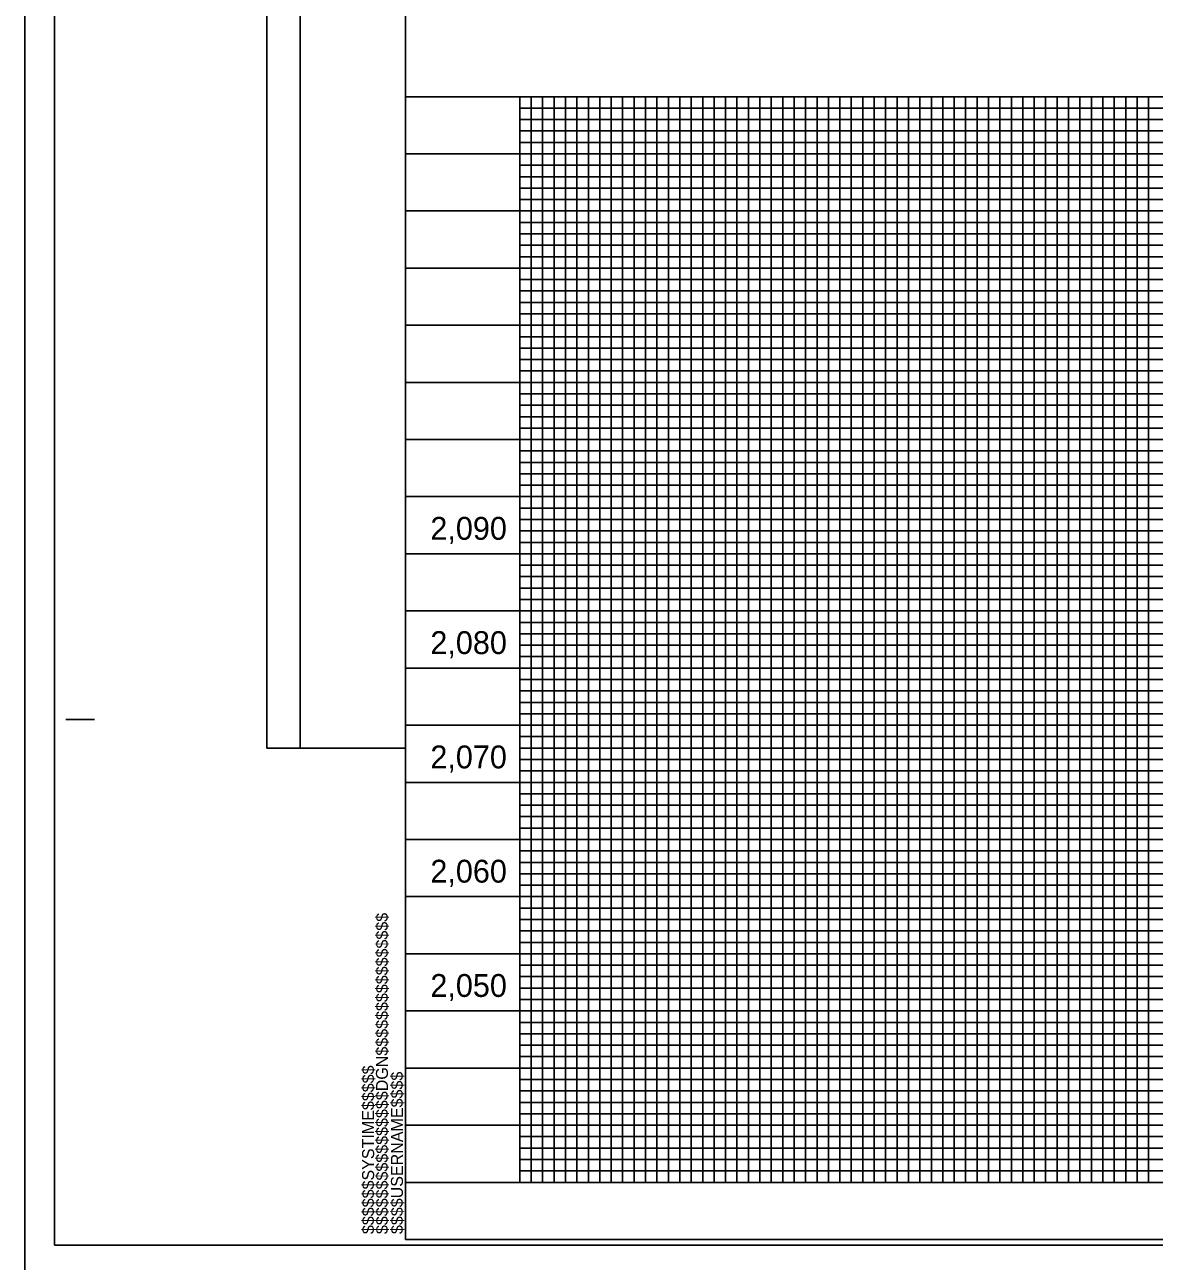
# Model space of a CAD drawing. Extents: x 757145 to 758829, y 592169 to 594973.
# Drawn here: x 757145 to 757639, y 592721 to 593262 of the extents above; entities that cross this region are included whole.
import ezdxf

# ---------------------------------------------------------------- set-up
doc = ezdxf.new("R2010")
doc.units = 0
for name, color, linetype in [('Exist Vertical Profile Vertical Axis Label', 7, 'Continuous'), ('Old_Level_63', 7, 'Continuous'), ('Prop Dimension', 7, 'Continuous'), ('Sheet Block System Information CELL', 7, 'Continuous'), ('Sheet Cutting Line CELL', 7, 'Continuous'), ('Sheet DOT Grid CELL', 7, 'Continuous'), ('Sheet Plan And Profile CELL', 7, 'Continuous'), ('Sheet Plot Border Inside CELL', 7, 'Continuous'), ('Sheet Plot Border Outside CELL', 7, 'Continuous'), ('Sheet Profile Grid Major CELL', 7, 'Continuous'), ('Sheet Profile Grid Middle CELL', 7, 'Continuous'), ('Sheet Profile Grid Minor CELL', 7, 'Continuous')]:
    doc.layers.add(name, color=color, linetype=linetype)

msp = doc.modelspace()

# ---------------------------------------------------------------- linework, layer by layer
at = {"layer": 'Exist Vertical Profile Vertical Axis Label'}
msp.add_line((757265.92, 592945.33), (757265.92, 593735.98), dxfattribs=at)
msp.add_lwpolyline([(757251.37, 592945.33), (757251.37, 593735.98), (757311.92, 593735.98), (757311.92, 592945.33)], close=True, dxfattribs=at)
at = {"layer": 'Prop Dimension'}
msp.add_lwpolyline([(757361.92, 593230.33), (758761.92, 593230.33), (758761.92, 592755.33), (757361.92, 592755.33)], close=True, dxfattribs=at)
at = {"layer": 'Sheet Block System Information CELL'}
msp.add_line((757311.92, 592730.33), (757311.92, 592730.33), dxfattribs=at)
at = {"layer": 'Sheet Cutting Line CELL'}
msp.add_line((757145.42, 593802.83), (757145.42, 592707.83), dxfattribs=at)
at = {"layer": 'Sheet DOT Grid CELL'}
for p, q in [((757311.92, 593230.33), (758811.92, 593230.33)), ((757361.92, 593230.33), (757361.92, 592755.33)), ((757411.92, 593230.33), (757411.92, 592755.33)), ((757461.92, 593230.33), (757461.92, 592755.33)), ((757511.92, 593230.33), (757511.92, 592755.33)), ((757561.92, 593230.33), (757561.92, 592755.33)), ((757611.92, 593230.33), (757611.92, 592755.33)), ((757311.92, 593180.33), (758811.92, 593180.33)), ((757311.92, 593130.33), (758811.92, 593130.33)), ((757311.92, 593080.33), (758811.92, 593080.33)), ((757311.92, 593030.33), (758811.92, 593030.33)), ((757311.92, 592980.33), (758811.92, 592980.33)), ((757311.92, 592930.33), (758811.92, 592930.33)), ((757311.92, 592880.33), (758811.92, 592880.33)), ((757311.92, 592830.33), (758811.92, 592830.33)), ((757311.92, 592780.33), (758811.92, 592780.33))]:
    msp.add_line(p, q, dxfattribs=at)
at = {"layer": 'Sheet Plan And Profile CELL'}
for p, q in [((757163.42, 592957.83), (757175.92, 592957.83)), ((758811.92, 592755.33), (757311.92, 592755.33)), ((757311.92, 592730.33), (757311.92, 592730.33)), ((757311.92, 592730.33), (757311.92, 592730.33)), ((757311.92, 592730.33), (757311.92, 592730.33)), ((757311.92, 592730.33), (757311.92, 592730.33)), ((757311.92, 592730.33), (757311.92, 592730.33))]:
    msp.add_line(p, q, dxfattribs=at)
msp.add_lwpolyline([(758811.92, 593780.33), (757311.92, 593780.33), (757311.92, 592730.33), (758811.92, 592730.33)], close=True, dxfattribs=at)
at = {"layer": 'Sheet Plot Border Inside CELL'}
msp.add_lwpolyline([(757158.42, 592727.83), (758824.42, 592727.83), (758824.42, 593782.83), (757158.42, 593782.83)], close=True, dxfattribs=at)
at = {"layer": 'Sheet Plot Border Outside CELL'}
msp.add_lwpolyline([(757145.42, 592707.83), (758828.92, 592707.83), (758828.92, 593802.83), (757145.42, 593802.83)], close=True, dxfattribs=at)
at = {"layer": 'Sheet Profile Grid Major CELL'}
for points in [[(757311.92, 593230.33), (758811.92, 593230.33)], [(757311.92, 593230.33), (757311.92, 592755.33)], [(757361.92, 592755.33), (757361.92, 593230.33), (757411.92, 593230.33), (757411.92, 592755.33)], [(757461.92, 592755.33), (757461.92, 593230.33), (757511.92, 593230.33), (757511.92, 592755.33)], [(757561.92, 592755.33), (757561.92, 593230.33), (757611.92, 593230.33), (757611.92, 592755.33)], [(758811.92, 593180.33), (757311.92, 593180.33), (757311.92, 593130.33), (758811.92, 593130.33)], [(758811.92, 593080.33), (757311.92, 593080.33), (757311.92, 593030.33), (758811.92, 593030.33)], [(758811.92, 592980.33), (757311.92, 592980.33), (757311.92, 592930.33), (758811.92, 592930.33)], [(758811.92, 592880.33), (757311.92, 592880.33), (757311.92, 592830.33), (758811.92, 592830.33)], [(758811.92, 592780.33), (757311.92, 592780.33)]]:
    msp.add_lwpolyline(points, dxfattribs=at)
at = {"layer": 'Sheet Profile Grid Middle CELL'}
for p, q in [((757311.92, 593205.33), (758811.92, 593205.33)), ((758811.92, 593155.33), (757311.92, 593155.33)), ((757311.92, 593155.33), (757311.92, 593105.33)), ((757311.92, 593105.33), (758811.92, 593105.33)), ((758811.92, 593055.33), (757311.92, 593055.33)), ((757311.92, 593055.33), (757311.92, 593005.33)), ((757311.92, 593005.33), (758811.92, 593005.33)), ((758811.92, 592955.33), (757311.92, 592955.33)), ((757311.92, 592955.33), (757311.92, 592905.33)), ((757311.92, 592905.33), (758811.92, 592905.33)), ((758811.92, 592855.33), (757311.92, 592855.33)), ((757311.92, 592855.33), (757311.92, 592805.33)), ((757311.92, 592805.33), (758811.92, 592805.33))]:
    msp.add_line(p, q, dxfattribs=at)
for points in [[(757386.92, 592755.33), (757386.92, 593230.33), (757436.92, 593230.33), (757436.92, 592755.33)], [(757486.92, 592755.33), (757486.92, 593230.33), (757536.92, 593230.33), (757536.92, 592755.33)], [(757586.92, 592755.33), (757586.92, 593230.33), (757636.92, 593230.33), (757636.92, 592755.33)]]:
    msp.add_lwpolyline(points, dxfattribs=at)
at = {"layer": 'Sheet Profile Grid Minor CELL'}
for points in [[(757366.92, 592755.33), (757366.92, 593230.33), (757371.92, 593230.33), (757371.92, 592755.33)], [(757376.92, 592755.33), (757376.92, 593230.33), (757381.92, 593230.33), (757381.92, 592755.33)], [(757391.92, 592755.33), (757391.92, 593230.33), (757396.92, 593230.33), (757396.92, 592755.33)], [(757401.92, 592755.33), (757401.92, 593230.33), (757406.92, 593230.33), (757406.92, 592755.33)], [(757416.92, 592755.33), (757416.92, 593230.33), (757421.92, 593230.33), (757421.92, 592755.33)], [(757426.92, 592755.33), (757426.92, 593230.33), (757431.92, 593230.33), (757431.92, 592755.33)], [(757441.92, 592755.33), (757441.92, 593230.33), (757446.92, 593230.33), (757446.92, 592755.33)], [(757451.92, 592755.33), (757451.92, 593230.33), (757456.92, 593230.33), (757456.92, 592755.33)], [(757466.92, 592755.33), (757466.92, 593230.33), (757471.92, 593230.33), (757471.92, 592755.33)], [(757476.92, 592755.33), (757476.92, 593230.33), (757481.92, 593230.33), (757481.92, 592755.33)], [(757491.92, 592755.33), (757491.92, 593230.33), (757496.92, 593230.33), (757496.92, 592755.33)], [(757501.92, 592755.33), (757501.92, 593230.33), (757506.92, 593230.33), (757506.92, 592755.33)], [(757516.92, 592755.33), (757516.92, 593230.33), (757521.92, 593230.33), (757521.92, 592755.33)], [(757526.92, 592755.33), (757526.92, 593230.33), (757531.92, 593230.33), (757531.92, 592755.33)], [(757541.92, 592755.33), (757541.92, 593230.33), (757546.92, 593230.33), (757546.92, 592755.33)], [(757551.92, 592755.33), (757551.92, 593230.33), (757556.92, 593230.33), (757556.92, 592755.33)], [(757566.92, 592755.33), (757566.92, 593230.33), (757571.92, 593230.33), (757571.92, 592755.33)], [(757576.92, 592755.33), (757576.92, 593230.33), (757581.92, 593230.33), (757581.92, 592755.33)], [(757591.92, 592755.33), (757591.92, 593230.33), (757596.92, 593230.33), (757596.92, 592755.33)], [(757601.92, 592755.33), (757601.92, 593230.33), (757606.92, 593230.33), (757606.92, 592755.33)], [(757616.92, 592755.33), (757616.92, 593230.33), (757621.92, 593230.33), (757621.92, 592755.33)], [(757626.92, 592755.33), (757626.92, 593230.33), (757631.92, 593230.33), (757631.92, 592755.33)], [(758761.92, 593225.33), (757361.92, 593225.33)], [(758761.92, 593215.33), (757361.92, 593215.33), (757361.92, 593220.33), (758761.92, 593220.33)], [(758761.92, 593200.33), (757361.92, 593200.33), (757361.92, 593205.33), (757361.92, 593210.33), (758761.92, 593210.33)], [(758761.92, 593190.33), (757361.92, 593190.33), (757361.92, 593195.33), (758761.92, 593195.33)], [(758761.92, 593175.33), (757361.92, 593175.33), (757361.92, 593180.33), (757361.92, 593185.33), (758761.92, 593185.33)], [(758761.92, 593165.33), (757361.92, 593165.33), (757361.92, 593170.33), (758761.92, 593170.33)], [(758761.92, 593150.33), (757361.92, 593150.33), (757361.92, 593155.33), (757361.92, 593160.33), (758761.92, 593160.33)], [(758761.92, 593140.33), (757361.92, 593140.33), (757361.92, 593145.33), (758761.92, 593145.33)], [(757361.92, 593125.33), (757361.92, 593130.33), (757361.92, 593135.33), (758761.92, 593135.33)], [(758761.92, 593120.33), (757361.92, 593120.33), (757361.92, 593125.33), (758761.92, 593125.33)], [(758761.92, 593110.33), (757361.92, 593110.33), (757361.92, 593115.33), (758761.92, 593115.33)], [(758761.92, 593095.33), (757361.92, 593095.33), (757361.92, 593100.33), (758761.92, 593100.33)], [(758761.92, 593085.33), (757361.92, 593085.33), (757361.92, 593090.33), (758761.92, 593090.33)], [(758761.92, 593070.33), (757361.92, 593070.33), (757361.92, 593075.33), (758761.92, 593075.33)], [(758761.92, 593060.33), (757361.92, 593060.33), (757361.92, 593065.33), (758761.92, 593065.33)], [(758761.92, 593045.33), (757361.92, 593045.33), (757361.92, 593050.33), (758761.92, 593050.33)], [(758761.92, 593035.33), (757361.92, 593035.33), (757361.92, 593040.33), (758761.92, 593040.33)], [(758761.92, 593020.33), (757361.92, 593020.33), (757361.92, 593025.33), (758761.92, 593025.33)], [(758761.92, 593010.33), (757361.92, 593010.33), (757361.92, 593015.33), (758761.92, 593015.33)], [(758761.92, 592995.33), (757361.92, 592995.33), (757361.92, 593000.33), (758761.92, 593000.33)], [(758761.92, 592985.33), (757361.92, 592985.33), (757361.92, 592990.33), (758761.92, 592990.33)], [(758761.92, 592970.33), (757361.92, 592970.33), (757361.92, 592975.33), (758761.92, 592975.33)], [(758761.92, 592960.33), (757361.92, 592960.33), (757361.92, 592965.33), (758761.92, 592965.33)], [(758761.92, 592945.33), (757361.92, 592945.33), (757361.92, 592950.33), (758761.92, 592950.33)], [(758761.92, 592935.33), (757361.92, 592935.33), (757361.92, 592940.33), (758761.92, 592940.33)], [(758761.92, 592920.33), (757361.92, 592920.33), (757361.92, 592925.33), (758761.92, 592925.33)], [(758761.92, 592910.33), (757361.92, 592910.33), (757361.92, 592915.33), (758761.92, 592915.33)], [(758761.92, 592895.33), (757361.92, 592895.33), (757361.92, 592900.33), (758761.92, 592900.33)], [(758761.92, 592885.33), (757361.92, 592885.33), (757361.92, 592890.33), (758761.92, 592890.33)], [(758761.92, 592870.33), (757361.92, 592870.33), (757361.92, 592875.33), (758761.92, 592875.33)], [(758761.92, 592860.33), (757361.92, 592860.33), (757361.92, 592865.33), (758761.92, 592865.33)], [(758761.92, 592845.33), (757361.92, 592845.33), (757361.92, 592850.33), (758761.92, 592850.33)], [(758761.92, 592835.33), (757361.92, 592835.33), (757361.92, 592840.33), (758761.92, 592840.33)], [(757361.92, 592820.33), (757361.92, 592825.33), (758761.92, 592825.33)], [(757361.92, 592760.33), (758761.92, 592760.33), (758761.92, 592765.33), (757361.92, 592765.33), (757361.92, 592770.33), (758761.92, 592770.33), (758761.92, 592775.33), (757361.92, 592775.33), (757361.92, 592780.33), (757361.92, 592785.33), (758761.92, 592785.33), (758761.92, 592790.33), (757361.92, 592790.33), (757361.92, 592795.33), (758761.92, 592795.33), (758761.92, 592800.33), (757361.92, 592800.33), (757361.92, 592805.33), (757361.92, 592810.33), (758761.92, 592810.33), (758761.92, 592815.33), (757361.92, 592815.33), (757361.92, 592820.33), (758761.92, 592820.33)]]:
    msp.add_lwpolyline(points, dxfattribs=at)

# ---------------------------------------------------------------- texts
at = {"layer": 'Old_Level_63'}
for s, p in [('2,090', (757322.82, 593036.46)), ('2,080', (757322.82, 592986.46)), ('2,070', (757322.82, 592936.46)), ('2,060', (757322.82, 592886.46)), ('2,050', (757322.82, 592836.46))]:
    msp.add_text(s, height=10, dxfattribs=at).set_placement(p)
at = {"layer": 'Sheet Block System Information CELL'}
for s, p in [('$$$$$$$$$$$$$$$$DGN$$$$$$$$$$$$$$$$', (757304.27, 592732.69)), ('$$$$$$SYSTIME$$$$$', (757298.22, 592732.69)), ('$$$$USERNAME$$$$', (757310.84, 592732.7))]:
    msp.add_text(s, height=5.25, rotation=90, dxfattribs=at).set_placement(p)

doc.saveas('drawing.dxf')
